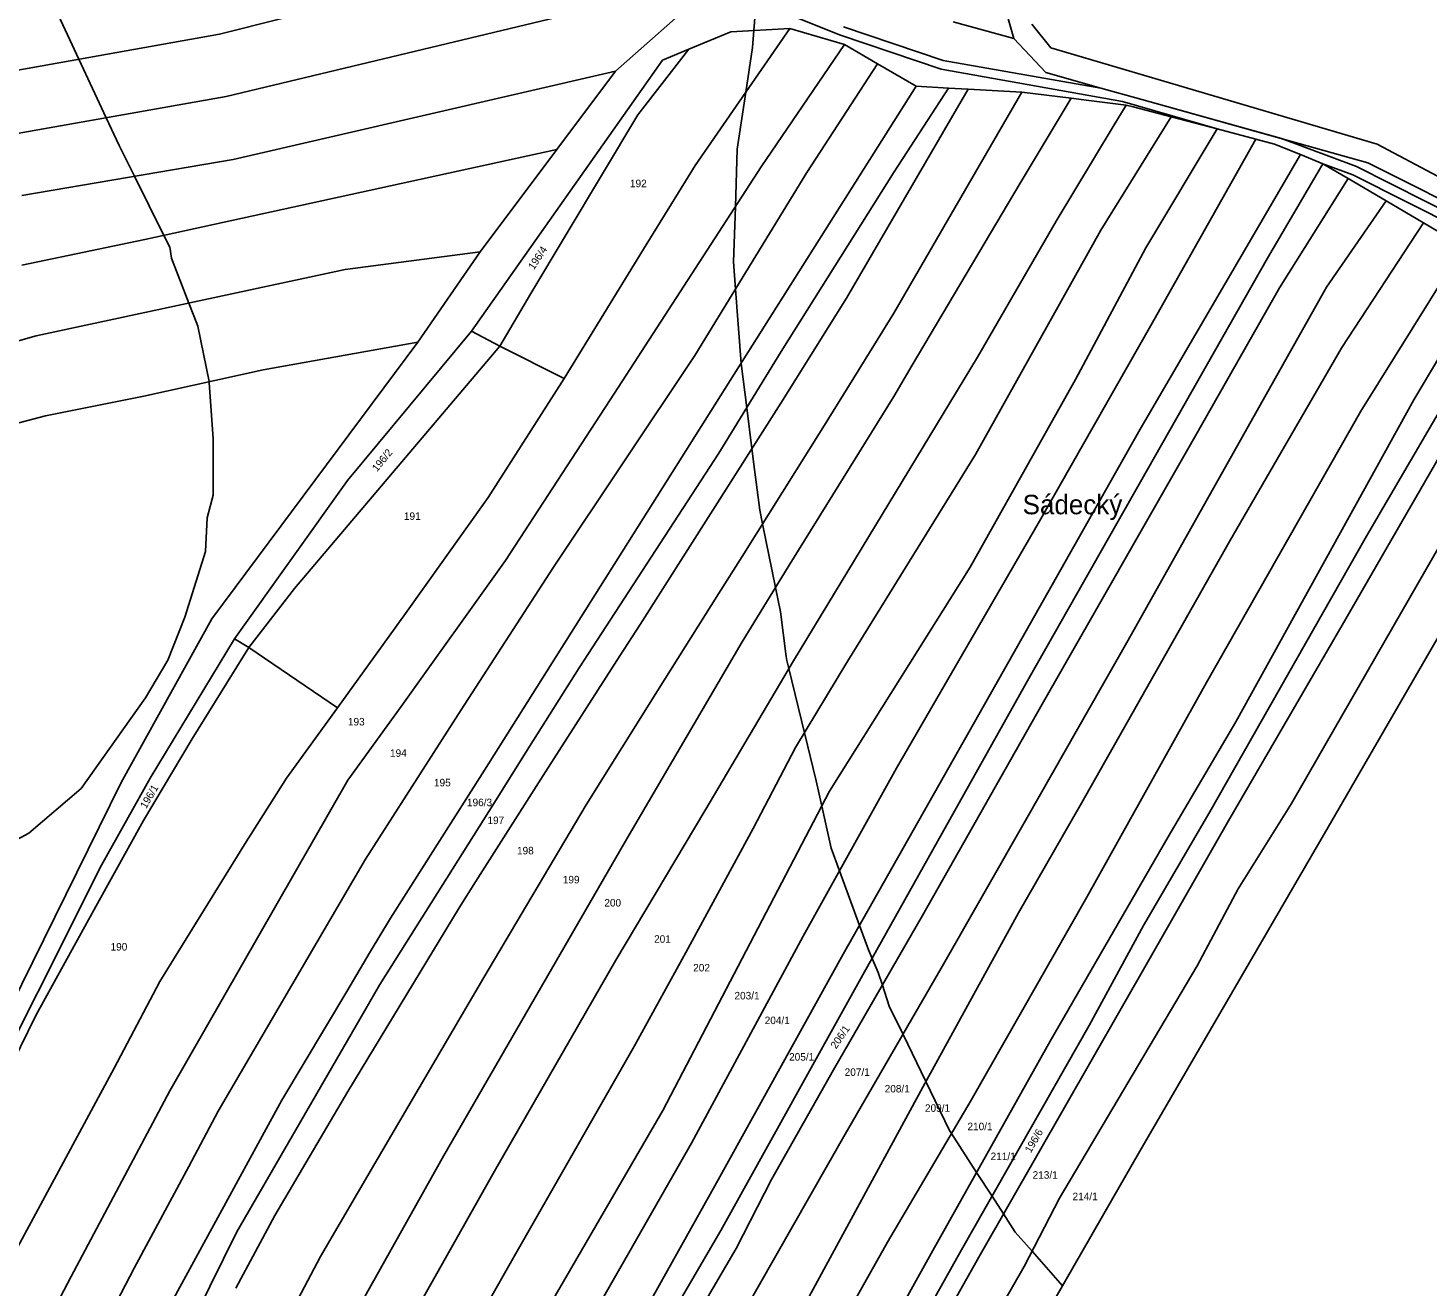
# Model space of a CAD drawing. Extents: x -749173 to -746119, y -1132678 to -1130338.
# Drawn here: x -747057.3 to -746740.4, y -1131608.6 to -1131323.7 of the extents above; entities that cross this region are included whole.
import ezdxf

# ---------------------------------------------------------------- set-up
doc = ezdxf.new("R2010")
doc.units = 0
for name, color, linetype in [('Vrstva 1', 7, 'Continuous'), ('Vrstva 13', 7, 'Continuous'), ('Vrstva 15', 7, 'Continuous'), ('Vrstva 18', 7, 'Continuous'), ('Vrstva 30', 7, 'Continuous'), ('Vrstva 52', 7, 'Continuous'), ('Vrstva 6', 7, 'Continuous')]:
    doc.layers.add(name, color=color, linetype=linetype)

msp = doc.modelspace()

# ---------------------------------------------------------------- linework, layer by layer
at = {"layer": 'Vrstva 1'}
for points in [[(-746924.29, -1131333.42), (-746904.32, -1131315.73)], [(-746834.16, -1131326.07), (-746836.61, -1131317.21)], [(-746884.86, -1131323.76), (-746898.19, -1131324.54)], [(-746872.46, -1131327.44), (-746884.86, -1131323.76)], [(-746847.85, -1131322.3), (-746834.16, -1131326.07)], [(-746830.08, -1131322.83), (-746825.76, -1131328.14)], [(-746898.19, -1131324.54), (-746907.72, -1131328.49)], [(-746826.92, -1131333.77), (-746834.16, -1131326.07)], [(-746907.72, -1131328.49), (-746913.61, -1131330.93)], [(-746864.98, -1131331.78), (-746872.46, -1131327.44)], [(-746825.76, -1131328.14), (-746809.36, -1131332.99)], [(-746913.61, -1131330.93), (-746956.91, -1131392.29)], [(-746937.58, -1131351.14), (-746924.29, -1131333.42)], [(-746856.2, -1131336.86), (-746864.98, -1131331.78)], [(-746809.36, -1131332.99), (-746800.16, -1131335.71)], [(-746848.88, -1131337.27), (-746856.2, -1131336.86)], [(-746814.45, -1131337.26), (-746826.92, -1131333.77)], [(-746800.16, -1131335.71), (-746751.91, -1131349.96)], [(-746844.5, -1131337.51), (-746848.88, -1131337.27)], [(-746832.31, -1131338.23), (-746844.5, -1131337.51)], [(-746821.13, -1131339.58), (-746832.31, -1131338.23)], [(-746817.14, -1131340.07), (-746821.13, -1131339.58)], [(-746805.12, -1131339.87), (-746814.45, -1131337.26)], [(-746753.98, -1131354.19), (-746805.12, -1131339.87)], [(-746808.72, -1131341.12), (-746817.14, -1131340.07)], [(-746807.11, -1131341.54), (-746808.72, -1131341.12)], [(-746798.54, -1131343.8), (-746807.11, -1131341.54)], [(-746788.13, -1131346.53), (-746798.54, -1131343.8)], [(-746779.33, -1131348.85), (-746788.13, -1131346.53)], [(-746775.13, -1131349.95), (-746779.33, -1131348.85)], [(-746954.94, -1131374.31), (-746937.58, -1131351.14)], [(-746769.23, -1131352.27), (-746775.13, -1131349.95)], [(-746764.19, -1131354.41), (-746769.23, -1131352.27)], [(-746751.91, -1131349.96), (-746724.6, -1131364.42)], [(-746758.48, -1131357.76), (-746764.19, -1131354.41)], [(-746726.64, -1131367.9), (-746753.98, -1131354.19)], [(-746749.89, -1131362.79), (-746758.48, -1131357.76)], [(-746741.44, -1131367.75), (-746749.89, -1131362.79)], [(-746732.32, -1131373.1), (-746741.44, -1131367.75)], [(-746969.05, -1131394.8), (-746954.94, -1131374.31)], [(-746956.91, -1131392.29), (-746984.94, -1131426.04)], [(-747015.63, -1131457.35), (-746969.05, -1131394.8)], [(-746984.94, -1131426.04), (-747010.5, -1131461.93)], [(-747036.2, -1131494.41), (-747015.63, -1131457.35)], [(-747010.5, -1131461.93), (-747029.58, -1131493.39)], [(-747071.24, -1131565.46), (-747036.2, -1131494.41)], [(-747029.58, -1131493.39), (-747040.61, -1131513.07)], [(-747040.61, -1131513.07), (-747069.58, -1131570.72)]]:
    msp.add_lwpolyline(points, dxfattribs=at)
at = {"layer": 'Vrstva 13'}
for points in [[(-746762.97, -1131504.51), (-746721.13, -1131432.18)], [(-746805.6, -1131577.83), (-746762.97, -1131504.51)], [(-746835.31, -1131629.56), (-746805.6, -1131577.83)]]:
    msp.add_lwpolyline(points, dxfattribs=at)
at = {"layer": 'Vrstva 30'}
for p, q in [((-746873.35, -1131325.27), (-746896.81, -1131315.91)), ((-746872.65, -1131323.39), (-746850.11, -1131331.05)), ((-746850.61, -1131332.99), (-746873.35, -1131325.27)), ((-746809.51, -1131340.28), (-746850.61, -1131332.99)), ((-746850.11, -1131331.05), (-746814.45, -1131337.26)), ((-746814.45, -1131337.26), (-746805.12, -1131339.87)), ((-746805.12, -1131339.87), (-746773.56, -1131348.71)), ((-746788.13, -1131346.53), (-746809.51, -1131340.28)), ((-746779.33, -1131348.85), (-746788.13, -1131346.53)), ((-746775.13, -1131349.95), (-746779.33, -1131348.85)), ((-746773.56, -1131348.71), (-746756.57, -1131355.05)), ((-746769.23, -1131352.27), (-746775.13, -1131349.95)), ((-746764.19, -1131354.41), (-746769.23, -1131352.27)), ((-746757.37, -1131356.89), (-746764.19, -1131354.41)), ((-746756.57, -1131355.05), (-746723.61, -1131371.7)), ((-746724.53, -1131373.48), (-746757.37, -1131356.89))]:
    msp.add_line(p, q, dxfattribs=at)
at = {"layer": 'Vrstva 52'}
for points in [[(-746892.06, -1131312.87), (-746892.99, -1131324.23), (-746893.31, -1131328.12), (-746894.82, -1131338.23), (-746896.75, -1131351.12), (-746897.16, -1131364.12), (-746897.56, -1131376.62), (-746897.11, -1131382.77), (-746895.87, -1131399.59), (-746894.59, -1131409.63), (-746893.41, -1131418.86), (-746892.8, -1131423.59), (-746891.62, -1131432.75), (-746890.99, -1131435.85), (-746888.06, -1131450.25), (-746886.94, -1131455.75), (-746885.69, -1131465.87), (-746885.47, -1131466.76), (-746885.02, -1131468.61), (-746881.5, -1131483.14), (-746878.87, -1131494), (-746878.2, -1131497.07), (-746877.6, -1131499.78), (-746875.5, -1131509.25), (-746873.59, -1131514.4), (-746869.03, -1131526.74), (-746867, -1131532.25), (-746866.17, -1131534.19), (-746864.81, -1131537.37), (-746863.87, -1131540.25), (-746862.31, -1131545), (-746859.2, -1131551.42), (-746854.04, -1131562.08), (-746848.69, -1131573.12), (-746848.23, -1131573.83), (-746842.54, -1131582.63), (-746839.04, -1131588.03), (-746836.47, -1131592.01), (-746833.81, -1131596.12), (-746830, -1131600.43), (-746823.08, -1131608.26)], [(-747083.87, -1131520.37), (-747057.06, -1131505.87), (-747045.19, -1131495.75), (-747030.69, -1131475.25), (-747025.62, -1131466.75), (-747021.75, -1131457), (-747017.06, -1131442.12), (-747016.69, -1131434.5), (-747015.37, -1131429.37), (-747015.37, -1131416.62), (-747016.25, -1131403.87), (-747016.28, -1131403.7), (-747018.81, -1131391.12), (-747019.71, -1131388.79), (-747020.83, -1131385.91), (-747024.75, -1131375.75), (-747025.19, -1131373.25), (-747026.5, -1131370.61), (-747033.16, -1131357.22), (-747036.62, -1131350.25), (-747039.55, -1131343.99), (-747045.74, -1131330.77), (-747051.44, -1131318.61)], [(-746721.13, -1131432.18), (-746762.97, -1131504.51), (-746805.6, -1131577.83), (-746823.08, -1131608.26)], [(-746823.08, -1131608.26), (-746834.63, -1131628.37)]]:
    msp.add_lwpolyline(points, dxfattribs=at)
at = {"layer": 'Vrstva 6'}
for points in [[(-747013.88, -1131325.1), (-746957.78, -1131310.91)], [(-746903.68, -1131313.1), (-747012.43, -1131339.18)], [(-746884.86, -1131323.76), (-746906.22, -1131354.79)], [(-747060.42, -1131333.39), (-747013.88, -1131325.1)], [(-746907.72, -1131328.49), (-746919.23, -1131343.31)], [(-746872.46, -1131327.44), (-746891.3, -1131355.07)], [(-747010.84, -1131353.43), (-746924.29, -1131333.42)], [(-746880.95, -1131356.37), (-746864.98, -1131331.78)], [(-746856.2, -1131336.86), (-746897.43, -1131402.02)], [(-747012.43, -1131339.18), (-747059.71, -1131347.57)], [(-746844.5, -1131337.51), (-746872, -1131384.8)], [(-746861.32, -1131388.21), (-746832.31, -1131338.23)], [(-746861.19, -1131356.24), (-746848.88, -1131337.27)], [(-746821.13, -1131339.58), (-746832.67, -1131358.76)], [(-746811.66, -1131346), (-746808.72, -1131341.12)], [(-746919.23, -1131343.31), (-746943.46, -1131383.74)], [(-746824.55, -1131367.37), (-746811.66, -1131346)], [(-746814.47, -1131369.41), (-746798.54, -1131343.8)], [(-746804.23, -1131373.45), (-746788.13, -1131346.53)], [(-746779.33, -1131348.85), (-746803.15, -1131391.01)], [(-746937.58, -1131351.14), (-747030.83, -1131371.56)], [(-746786.36, -1131381.65), (-746769.23, -1131352.27)], [(-747058.66, -1131361.56), (-747010.84, -1131353.43)], [(-746891.3, -1131355.07), (-746924.52, -1131406.32)], [(-746906.22, -1131354.79), (-746917.97, -1131373.69)], [(-746764.19, -1131354.41), (-746776.73, -1131375.73)], [(-746906.3, -1131397.79), (-746880.95, -1131356.37)], [(-746886.76, -1131396.86), (-746861.19, -1131356.24)], [(-746857.11, -1131399.99), (-746832.67, -1131358.76)], [(-746773.98, -1131382.51), (-746758.48, -1131357.76)], [(-746749.89, -1131362.79), (-746763.35, -1131382.36)], [(-746842.36, -1131398.13), (-746824.55, -1131367.37)], [(-746759.87, -1131395.96), (-746741.44, -1131367.75)], [(-747030.83, -1131371.56), (-747058.64, -1131377.38)], [(-746842.83, -1131420.22), (-746814.47, -1131369.41)], [(-746985.47, -1131378.34), (-746954.94, -1131374.31)], [(-746917.97, -1131373.69), (-746935.88, -1131402.96)], [(-746820.17, -1131403.25), (-746804.23, -1131373.45)], [(-746732.32, -1131373.1), (-746755.61, -1131410.4)], [(-746776.73, -1131375.73), (-746810.85, -1131435.82)], [(-746743.56, -1131407.78), (-746725.23, -1131377.02)], [(-747055.44, -1131393.32), (-746985.47, -1131378.34)], [(-746719.96, -1131379.93), (-746754.34, -1131438.63)], [(-746943.46, -1131383.74), (-746950.48, -1131395.66)], [(-746805.54, -1131414.43), (-746786.36, -1131381.65)], [(-746792.97, -1131415.79), (-746773.98, -1131382.51)], [(-746763.35, -1131382.36), (-746792.36, -1131433.87)], [(-746872, -1131384.8), (-746886.86, -1131408.57)], [(-746871.32, -1131404.39), (-746861.32, -1131388.21)], [(-747097.83, -1131405.44), (-747055.44, -1131393.32)], [(-746950.48, -1131395.66), (-746956.91, -1131392.29)], [(-746803.15, -1131391.01), (-746828.65, -1131435.77)], [(-746969.05, -1131394.8), (-747004.04, -1131401.01)], [(-746950.48, -1131395.66), (-746996.95, -1131450.51)], [(-746935.88, -1131402.96), (-746950.48, -1131395.66)], [(-746900.9, -1131419.92), (-746886.76, -1131396.86)], [(-746785.31, -1131439.88), (-746759.87, -1131395.96)], [(-746938.3, -1131445.7), (-746906.3, -1131397.79)], [(-746883.99, -1131466.86), (-746842.36, -1131398.13)], [(-746857.11, -1131399.99), (-746861.28, -1131407.04)], [(-747004.04, -1131401.01), (-747031.06, -1131406.95)], [(-746897.43, -1131402.02), (-746953.97, -1131491.61)], [(-746935.88, -1131402.96), (-746953.08, -1131429.89)], [(-746844.04, -1131445.67), (-746820.17, -1131403.25)], [(-746759.79, -1131458.77), (-746727.58, -1131402.99)], [(-746924.52, -1131406.32), (-746949.19, -1131444.14)], [(-746877.35, -1131414.14), (-746871.32, -1131404.39)], [(-747031.06, -1131406.95), (-747053.29, -1131411.45)], [(-746886.86, -1131408.57), (-746918.73, -1131458.64)], [(-746861.28, -1131407.04), (-746885.22, -1131445.58)], [(-746783.9, -1131480.65), (-746743.56, -1131407.78)], [(-747053.29, -1131411.45), (-747097.28, -1131423.01)], [(-746755.61, -1131410.4), (-746790.54, -1131471.76)], [(-746895.63, -1131443.23), (-746877.35, -1131414.14)], [(-746835.26, -1131467.04), (-746805.54, -1131414.43)], [(-746827.75, -1131476.66), (-746792.97, -1131415.79)], [(-746932.5, -1131468.46), (-746900.9, -1131419.92)], [(-746871.73, -1131466.88), (-746842.83, -1131420.22)], [(-746953.08, -1131429.89), (-746971.8, -1131456.19)], [(-746792.36, -1131433.87), (-746808.23, -1131462.22)], [(-746828.65, -1131435.77), (-746860.71, -1131491.16)], [(-746810.85, -1131435.82), (-746830.68, -1131470.71)], [(-746735.03, -1131436.04), (-746771.27, -1131499.19)], [(-746818.81, -1131499.06), (-746785.31, -1131439.88)], [(-746754.34, -1131438.63), (-746789.74, -1131501.01)], [(-746949.19, -1131444.14), (-746972.78, -1131477.2)], [(-746900.96, -1131451.69), (-746895.63, -1131443.23)], [(-746959.19, -1131477.95), (-746938.3, -1131445.7)], [(-746885.22, -1131445.58), (-746895.58, -1131462.61)], [(-746875.82, -1131496.38), (-746844.04, -1131445.67)], [(-746996.95, -1131450.51), (-747007.29, -1131463.85)], [(-746914.81, -1131473.69), (-746900.96, -1131451.69)], [(-746971.8, -1131456.19), (-746987.19, -1131477.53)], [(-746918.73, -1131458.64), (-746923.29, -1131465.74)], [(-746785.77, -1131503.44), (-746759.79, -1131458.77)], [(-747010.5, -1131461.93), (-747007.29, -1131463.85)], [(-746895.58, -1131462.61), (-746922.22, -1131508.08)], [(-746808.23, -1131462.22), (-746831.17, -1131502.49)], [(-747007.29, -1131463.85), (-747020.13, -1131484.49)], [(-746987.19, -1131477.53), (-747007.29, -1131463.85)], [(-746923.29, -1131465.74), (-746940.13, -1131491.96)], [(-746943.76, -1131486.29), (-746932.5, -1131468.46)], [(-746904.03, -1131500.8), (-746883.99, -1131466.86)], [(-746883.53, -1131486.51), (-746871.73, -1131466.88)], [(-746872.72, -1131533.26), (-746835.26, -1131467.04)], [(-746830.68, -1131470.71), (-746868.27, -1131537.95)], [(-746790.54, -1131471.76), (-746817.59, -1131520.32)], [(-746930.93, -1131499.45), (-746914.81, -1131473.69)], [(-746987.19, -1131477.53), (-746998.71, -1131493.41)], [(-746972.78, -1131477.2), (-746984.84, -1131493.86)], [(-746980.89, -1131511.72), (-746959.19, -1131477.95)], [(-746854.79, -1131524.52), (-746827.75, -1131476.66)], [(-746799.17, -1131506.71), (-746783.9, -1131480.65)], [(-747020.13, -1131484.49), (-747031.12, -1131502.98)], [(-746952.97, -1131500.95), (-746943.76, -1131486.29)], [(-746893.15, -1131504.79), (-746883.53, -1131486.51)], [(-746953.97, -1131491.61), (-746975.21, -1131525.11)], [(-746940.13, -1131491.96), (-746955.95, -1131516.9)], [(-746860.71, -1131491.16), (-746881.78, -1131529.17)], [(-746984.84, -1131493.86), (-747025.18, -1131564.19)], [(-746998.71, -1131493.41), (-747008.22, -1131508.42)], [(-746913.55, -1131568.61), (-746875.82, -1131496.38)], [(-746977.6, -1131540.14), (-746952.97, -1131500.95)], [(-746954.07, -1131538.52), (-746930.93, -1131499.45)], [(-746924.23, -1131534.57), (-746904.03, -1131500.8)], [(-746833.09, -1131523.91), (-746818.81, -1131499.06)], [(-746789.74, -1131501.01), (-746804.77, -1131526.77)], [(-746771.27, -1131499.19), (-746783.34, -1131518.48)], [(-747031.12, -1131502.98), (-747041.56, -1131521.76)], [(-746908.36, -1131532.89), (-746893.15, -1131504.79)], [(-746831.17, -1131502.49), (-746850.31, -1131536.07)], [(-746803.56, -1131534.6), (-746785.77, -1131503.44)], [(-746825.91, -1131552.9), (-746799.17, -1131506.71)], [(-747008.22, -1131508.42), (-747027.4, -1131539.4)], [(-746922.22, -1131508.08), (-746963.1, -1131578.77)], [(-747014.2, -1131568.8), (-746980.89, -1131511.72)], [(-746955.95, -1131516.9), (-746959.67, -1131522.76)], [(-746817.59, -1131520.32), (-746843.79, -1131566.28)], [(-746783.34, -1131518.48), (-746792.61, -1131535.89)], [(-747041.56, -1131521.76), (-747055.38, -1131546.97)], [(-746959.67, -1131522.76), (-746984.88, -1131564.32)], [(-746975.21, -1131525.11), (-746979.78, -1131532.75)], [(-746874.92, -1131559.39), (-746854.79, -1131524.52)], [(-746854.73, -1131563.34), (-746833.09, -1131523.91)], [(-746804.77, -1131526.77), (-746817.08, -1131549.42)], [(-746881.78, -1131529.17), (-746907.08, -1131576)], [(-746979.78, -1131532.75), (-746985.12, -1131541.69)], [(-746919.98, -1131553.97), (-746908.36, -1131532.89)], [(-746901.46, -1131584.95), (-746872.72, -1131533.26)], [(-746951.39, -1131581.85), (-746924.23, -1131534.57)], [(-746850.31, -1131536.07), (-746872.27, -1131573.98)], [(-746841.77, -1131601.25), (-746803.56, -1131534.6)], [(-746792.61, -1131535.89), (-746823.76, -1131588.48)], [(-747027.4, -1131539.4), (-747037.75, -1131559.03)], [(-746978.19, -1131579.68), (-746954.07, -1131538.52)], [(-746868.27, -1131537.95), (-746900.47, -1131595.76)], [(-746985.12, -1131541.69), (-746999.79, -1131566.27)], [(-746982.14, -1131547.97), (-746977.6, -1131540.14)], [(-747055.38, -1131546.97), (-747067.9, -1131572.38)], [(-747010.02, -1131596.06), (-746982.14, -1131547.97)], [(-746817.08, -1131549.42), (-746845.95, -1131600.18)], [(-746947.17, -1131601.52), (-746919.98, -1131553.97)], [(-746852.43, -1131600.31), (-746825.91, -1131552.9)], [(-747037.75, -1131559.03), (-747059.66, -1131599.64)], [(-746888.97, -1131584.23), (-746874.92, -1131559.39)], [(-747025.18, -1131564.19), (-747047.5, -1131606.16)], [(-746984.88, -1131564.32), (-747001.37, -1131592.36)], [(-746888.6, -1131625.72), (-746854.73, -1131563.34)], [(-746999.79, -1131566.27), (-747003.78, -1131573.59)], [(-746843.79, -1131566.28), (-746862.7, -1131598.42)], [(-747020.87, -1131581.25), (-747014.2, -1131568.8)], [(-746954.43, -1131638.96), (-746913.55, -1131568.61)], [(-747003.78, -1131573.59), (-747030.22, -1131622.02)], [(-746872.27, -1131573.98), (-746895.97, -1131615.54)], [(-746907.08, -1131576), (-746938.41, -1131630.76)], [(-746991.07, -1131601.65), (-746978.19, -1131579.68)], [(-746963.1, -1131578.77), (-746987.05, -1131621.46)], [(-747033.2, -1131604.29), (-747020.87, -1131581.25)], [(-746988.51, -1131647.63), (-746951.39, -1131581.85)], [(-746927.2, -1131631.17), (-746901.46, -1131584.95)], [(-746896.94, -1131599.81), (-746888.97, -1131584.23)], [(-746823.76, -1131588.48), (-746831.81, -1131603.9)], [(-747001.37, -1131592.36), (-747010.19, -1131608.84)], [(-747040.44, -1131657.76), (-747010.02, -1131596.06)], [(-746900.47, -1131595.76), (-746930.93, -1131647.96)], [(-746914.93, -1131630.57), (-746896.94, -1131599.81)], [(-746862.7, -1131598.42), (-746885.19, -1131638.39)], [(-747010.61, -1131638.67), (-746991.07, -1131601.65)], [(-746963.82, -1131630.88), (-746947.17, -1131601.52)], [(-746890.72, -1131669.08), (-746852.43, -1131600.31)], [(-746873.6, -1131657.79), (-746841.77, -1131601.25)], [(-746845.95, -1131600.18), (-746871.48, -1131645.69)], [(-747047.5, -1131606.16), (-747055.87, -1131622.19)], [(-747038.23, -1131613.87), (-747033.2, -1131604.29)], [(-746831.81, -1131603.9), (-746856.95, -1131647.82)]]:
    msp.add_lwpolyline(points, dxfattribs=at)

# ---------------------------------------------------------------- texts
at = {"layer": 'Vrstva 15'}
msp.add_text('Sádecký', height=4.4, dxfattribs=at).set_placement((-746832.14, -1131433.71))
at = {"layer": 'Vrstva 18'}
for s, p in [('192', (-746921.01, -1131359.71)), ('191', (-746972.17, -1131434.99)), ('193', (-746984.85, -1131481.49)), ('194', (-746975.32, -1131488.59)), ('195', (-746965.37, -1131495.27)), ('196/3', (-746957.9, -1131499.76)), ('197', (-746953.27, -1131503.81)), ('198', (-746946.58, -1131510.66)), ('199', (-746936.21, -1131517.23)), ('200', (-746926.81, -1131522.46)), ('201', (-746915.55, -1131530.66)), ('190', (-747038.57, -1131532.43)), ('202', (-746906.7, -1131537.16)), ('203/1', (-746897.36, -1131543.48)), ('204/1', (-746890.52, -1131549.07)), ('205/1', (-746884.99, -1131557.33)), ('207/1', (-746872.41, -1131560.78)), ('208/1', (-746863.36, -1131564.53)), ('209/1', (-746854.24, -1131568.91)), ('210/1', (-746844.62, -1131573.08)), ('211/1', (-746839.39, -1131579.83)), ('213/1', (-746829.88, -1131584.05)), ('214/1', (-746820.84, -1131588.91))]:
    msp.add_text(s, height=1.7, dxfattribs=at).set_placement(p)
for s, rotation, p in [('196/4', 56.6574, (-746942.77, -1131378.53)), ('196/2', 50.4219, (-746978.26, -1131424.19)), ('196/1', 59.9315, (-747030.51, -1131500.46)), ('206/1', 55.8855, (-746874.35, -1131554.8)), ('196/6', 59.883, (-746830.29, -1131578.35))]:
    msp.add_text(s, height=1.7, rotation=rotation, dxfattribs=at).set_placement(p)

doc.saveas('drawing.dxf')
